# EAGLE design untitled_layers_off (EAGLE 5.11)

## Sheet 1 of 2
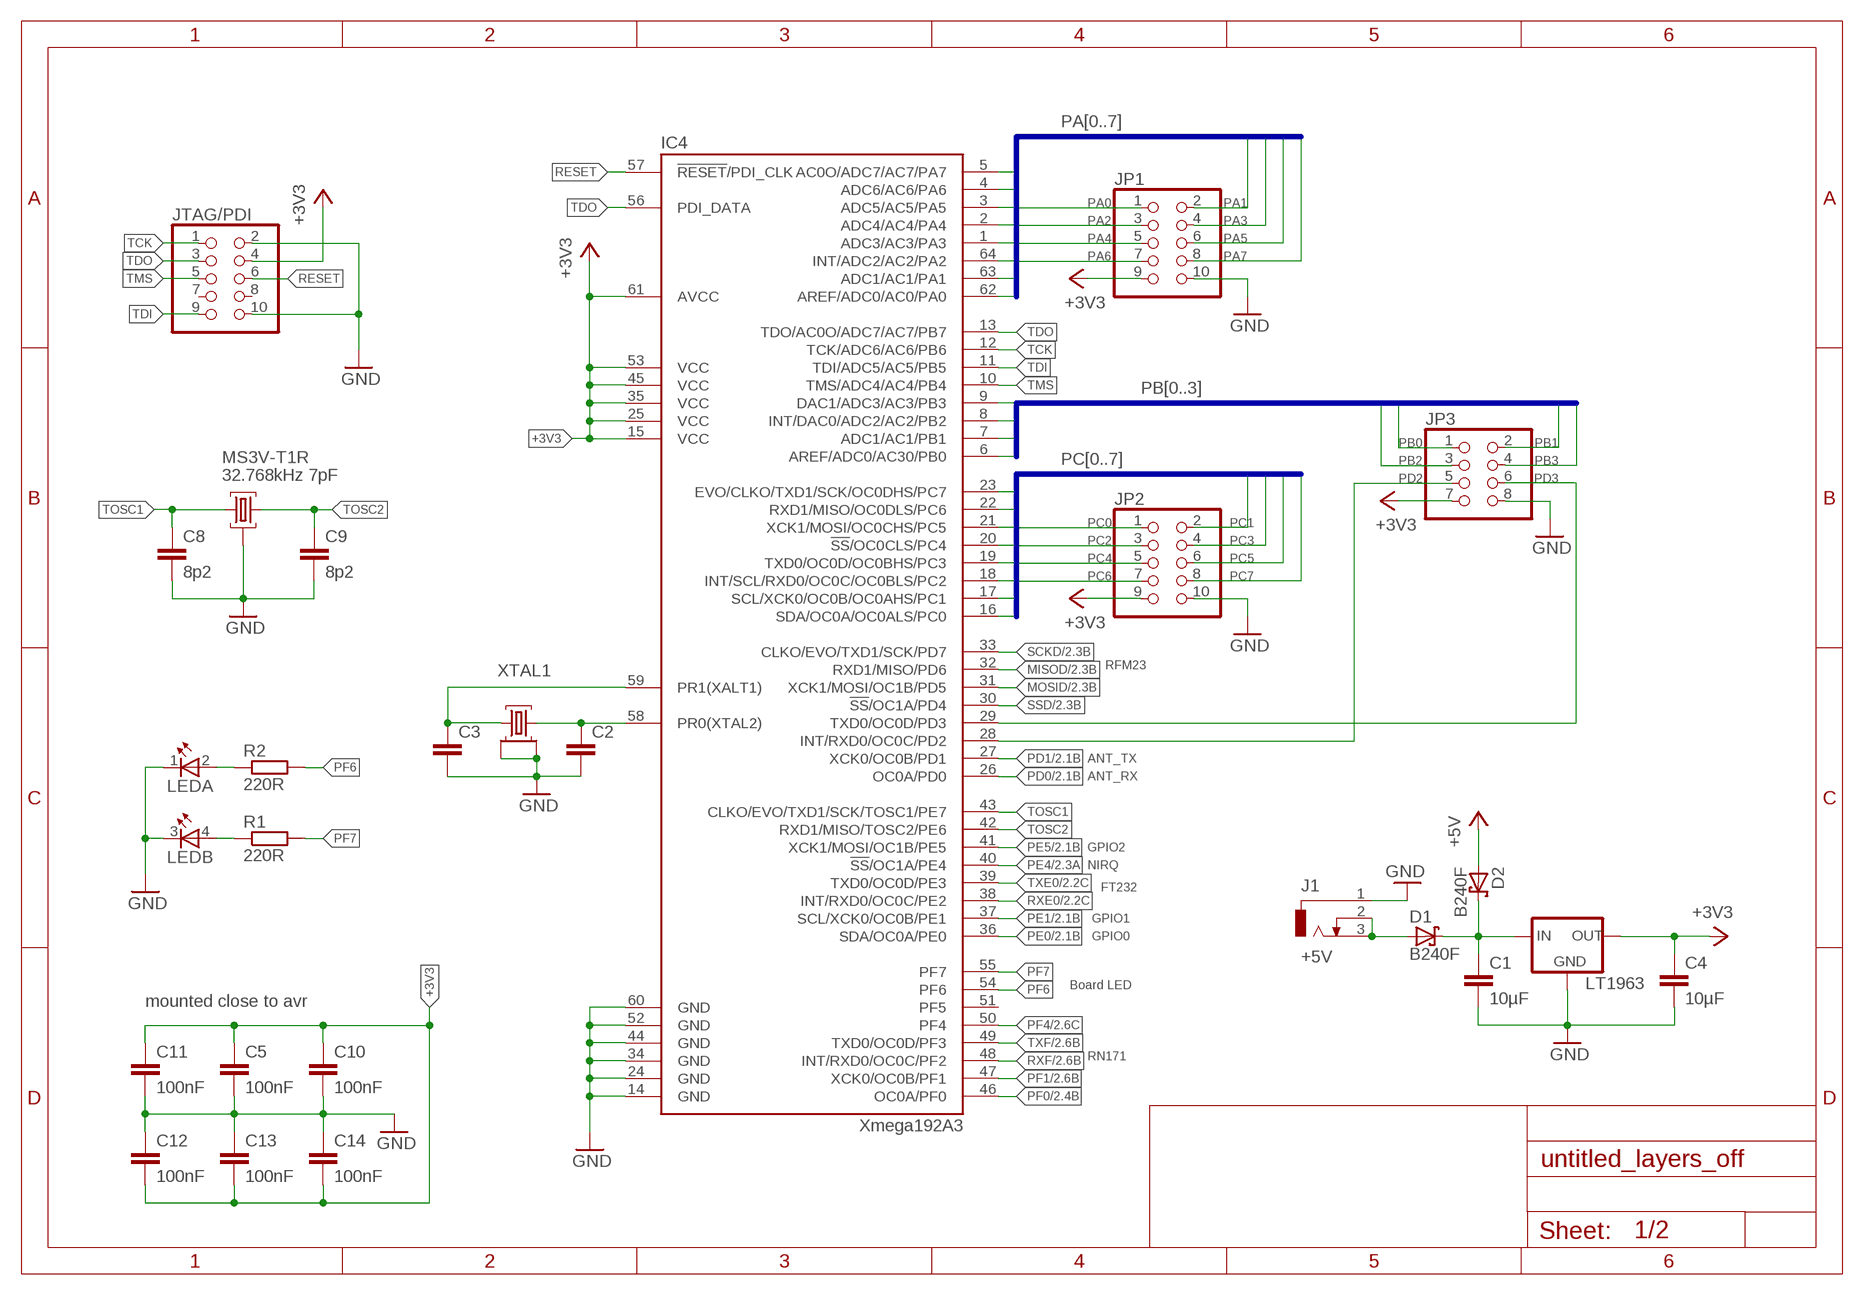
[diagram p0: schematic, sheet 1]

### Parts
C1  10µF  C-EUC1206  [C1206]
C2  C-EUC0805  [C0805]
C3  C-EUC0805  [C0805]
C4  10µF  C-EUC1206  [C1206]
C5  100nF  C-EUC0805  [C0805]
C8  8p2  C-EUC0805  [C0805]
C9  8p2  C-EUC0805  [C0805]
C10  100nF  C-EUC0805  [C0805]
C11  100nF  C-EUC0805  [C0805]
C12  100nF  C-EUC0805  [C0805]
C13  100nF  C-EUC0805  [C0805]
C14  100nF  C-EUC0805  [C0805]
D1  B240F  SCHOTTKY-DIODESMD  [SMB]
D2  B240F  SCHOTTKY-DIODESMD  [SMB]
IC4  Xmega192A3  ATXMEGA##A3-64A  [TQFP-64]
J1  +5V  DCJ0202  [DCJ0202]
JP1  PINHD-2X5  [2X05]
JP2  PINHD-2X5  [2X05]
JP3  PINHD-2X4  [2X04]
JTAG/PDI  PINHD-2X5/90  [2X05/90]
LED  TOPLED-2-/  [P-LCC-4/2]
LT1963  V_REG_MIC2920  [SOT223]
MS3V-T1R  32.768kHz 7pF  MS3V-T1R  [MS3V-T1R]
R1  220R  R-EU_R0805  [R0805]
R2  220R  R-EU_R0805  [R0805]
XTAL1  EUROQUARTZ-MT  [EUROQUARTZ-MT]

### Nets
+3V3: C4.1 C5.1 C10.1 C11.1 C12.2 C13.2 C14.2 IC4.15(VCC) IC4.25(VCC) IC4.35(VCC) IC4.45(VCC) IC4.53(VCC) IC4.61(AVCC) JP1.9 JP2.9 JP3.7 JTAG/PDI.4 LT1963.3(OUT) ; also sheet 2
+5V: D2.A ; also sheet 2
GND: C1.2 C2.2 C3.2 C4.2 C5.2 C8.2 C9.2 C10.2 C11.2 C12.1 C13.1 C14.1 IC4.14(GND) IC4.24(GND) IC4.34(GND) IC4.44(GND) IC4.52(GND) IC4.60(GND) J1.1 JP1.10 JP2.10 JP3.8 JTAG/PDI.2 JTAG/PDI.10 LED.1(A:C) LED.3(B:C) LT1963.2(GND) MS3V-T1R.TOP XTAL1.GND1 XTAL1.GND2 ; also sheet 2
MISOD: IC4.32(RXD1/MISO/PD6) ; also sheet 2
MOSID: IC4.31(XCK1/MOSI/OC1B/PD5) ; also sheet 2
N$1: LED.2(A:A) R2.1
N$2: D1.A J1.2 J1.3
N$3: C3.1 IC4.59(PR1(XALT1)) XTAL1.1
N$4: C2.1 IC4.58(PR0(XTAL2)) XTAL1.4
N$7: C1.1 D1.C D2.C LT1963.1(IN)
N$8: LED.4(B:A) R1.1
PA0: IC4.62(AREF/ADC0/AC0/PA0) JP1.1
PA1: IC4.63(ADC1/AC1/PA1) JP1.2
PA2: IC4.64(INT/ADC2/AC2/PA2) JP1.3
PA3: IC4.1(ADC3/AC3/PA3) JP1.4
PA4: IC4.2(ADC4/AC4/PA4) JP1.5
PA5: IC4.3(ADC5/AC5/PA5) JP1.6
PA6: IC4.4(ADC6/AC6/PA6) JP1.7
PA7: IC4.5(AC0O/ADC7/AC7/PA7) JP1.8
PB0: IC4.6(AREF/ADC0/AC30/PB0) JP3.1
PB1: IC4.7(ADC1/AC1/PB1) JP3.2
PB2: IC4.8(INT/DAC0/ADC2/AC2/PB2) JP3.3
PB3: IC4.9(DAC1/ADC3/AC3/PB3) JP3.4
PC0: IC4.16(SDA/OC0A/OC0ALS/PC0) JP2.1
PC1: IC4.17(SCL/XCK0/OC0B/OC0AHS/PC1) JP2.2
PC2: IC4.18(INT/SCL/RXD0/OC0C/OC0BLS/PC2) JP2.3
PC3: IC4.19(TXD0/OC0D/OC0BHS/PC3) JP2.4
PC4: IC4.20(!SS!/OC0CLS/PC4) JP2.5
PC5: IC4.21(XCK1/MOSI/OC0CHS/PC5) JP2.6
PC6: IC4.22(RXD1/MISO/OC0DLS/PC6) JP2.7
PC7: IC4.23(EVO/CLKO/TXD1/SCK/OC0DHS/PC7) JP2.8
PD0: IC4.26(OC0A/PD0) ; also sheet 2
PD1: IC4.27(XCK0/OC0B/PD1) ; also sheet 2
PD2: IC4.28(INT/RXD0/OC0C/PD2) JP3.5
PD3: IC4.29(TXD0/OC0D/PD3) JP3.6
PE0: IC4.36(SDA/OC0A/PE0) ; also sheet 2
PE1: IC4.37(SCL/XCK0/OC0B/PE1) ; also sheet 2
PE4: IC4.40(!SS!/OC1A/PE4) ; also sheet 2
PE5: IC4.41(XCK1/MOSI/OC1B/PE5) ; also sheet 2
PF0: IC4.46(OC0A/PF0) ; also sheet 2
PF1: IC4.47(XCK0/OC0B/PF1) ; also sheet 2
PF4: IC4.50(PF4) ; also sheet 2
PF6: IC4.54(PF6) R2.2
PF7: IC4.55(PF7) R1.2
RESET: IC4.57(!RESET!/PDI_CLK) JTAG/PDI.6
RXE0: IC4.38(INT/RXD0/OC0C/PE2) ; also sheet 2
RXF: IC4.48(INT/RXD0/OC0C/PF2) ; also sheet 2
SCKD: IC4.33(CLKO/EVO/TXD1/SCK/PD7) ; also sheet 2
SSD: IC4.30(!SS!/OC1A/PD4) ; also sheet 2
TCK: IC4.12(TCK/ADC6/AC6/PB6) JTAG/PDI.1
TDI: IC4.11(TDI/ADC5/AC5/PB5) JTAG/PDI.9
TDO: IC4.13(TDO/AC0O/ADC7/AC7/PB7) IC4.56(PDI_DATA) JTAG/PDI.3
TMS: IC4.10(TMS/ADC4/AC4/PB4) JTAG/PDI.5
TOSC1: C8.1 IC4.43(CLKO/EVO/TXD1/SCK/TOSC1/PE7) MS3V-T1R.P$2
TOSC2: C9.1 IC4.42(RXD1/MISO/TOSC2/PE6) MS3V-T1R.P$3
TXE0: IC4.39(TXD0/OC0D/PE3) ; also sheet 2
TXF: IC4.49(TXD0/OC0D/PF3) ; also sheet 2
Unconnected: IC4.51(PF5) JTAG/PDI.7 JTAG/PDI.8

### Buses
PA[0..7]
PC[0..7]
PB[0..3]

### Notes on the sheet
- RFM23
- ANT_TX
- ANT_RX
- GPIO2
- NIRQ
- FT232
- GPIO1
- GPIO0
- Board LED
- mounted close to avr
- RN171

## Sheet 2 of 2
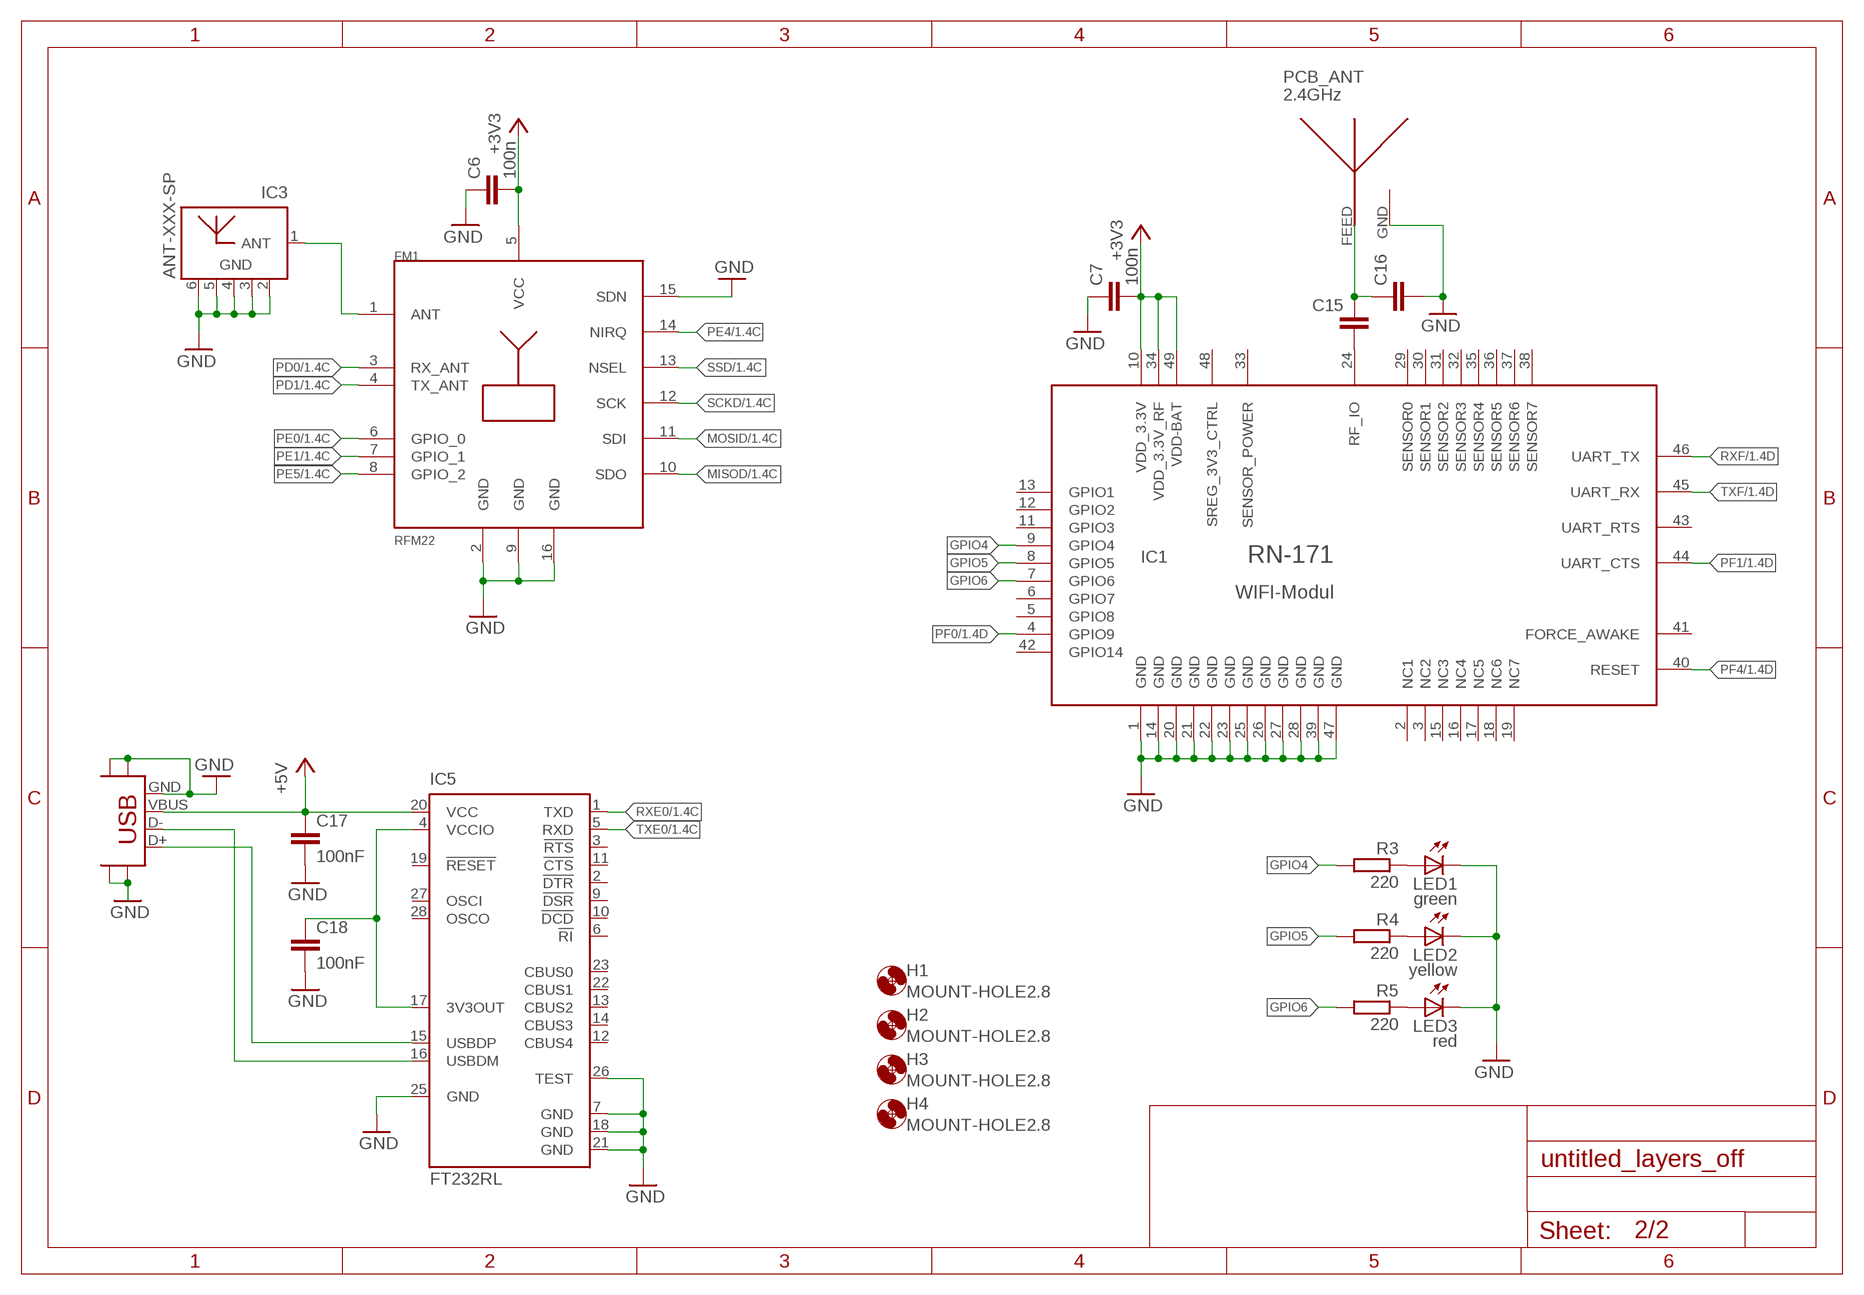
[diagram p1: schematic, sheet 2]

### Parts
C6  100n  C-EUC0805  [C0805]
C7  100n  C-EUC0805  [C0805]
C15  C-EUC0805  [C0805]
C16  C-EUC0805  [C0805]
C17  100nF  C-EUC0805  [C0805]
C18  100nF  C-EUC0805  [C0805]
FM1  RFM22  [RFM22]
H1  MOUNT-HOLE2.8  [2,8]
H2  MOUNT-HOLE2.8  [2,8]
H3  MOUNT-HOLE2.8  [2,8]
H4  MOUNT-HOLE2.8  [2,8]
IC1  RN-171  [RN-171]
IC3  ANT-XXX-SP  [ANT-XXX-SP]
IC5  FT232RL  [SSOP28]
LED1  green  LEDCHIPLED_0805  [CHIPLED_0805]
LED2  yellow  LEDCHIPLED_0805  [CHIPLED_0805]
LED3  red  LEDCHIPLED_0805  [CHIPLED_0805]
PCB_ANT  2.4GHz  ANT_2G4  [ANT_2G4]
R3  220  R-EU_R0805  [R0805]
R4  220  R-EU_R0805  [R0805]
R5  220  R-EU_R0805  [R0805]
X2  USBSMD  [USB-MINIB]

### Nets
+3V3: C6.2 C7.2 FM1.5(VCC) IC1.10(VDD_3.3V) IC1.34(VDD_3.3V_RF) IC1.49(VDD-BAT) ; also sheet 1
+5V: C17.1 IC5.20(VCC) X2.VBUS ; also sheet 1
GND: C6.1 C7.1 C16.2 C17.2 C18.2 FM1.2(GND) FM1.9(GND) FM1.15(SDN) FM1.16(GND) IC1.1(GND) IC1.14(GND) IC1.20(GND) IC1.21(GND) IC1.22(GND) IC1.23(GND) IC1.25(GND) IC1.26(GND) IC1.27(GND) IC1.28(GND) IC1.39(GND) IC1.47(GND) IC3.2(GND) IC3.3(GND) IC3.4(GND) IC3.5(GND) IC3.6(GND) IC5.7(GND) IC5.18(GND) IC5.21(GND) IC5.25(GND) IC5.26(TEST) LED1.C LED2.C LED3.C PCB_ANT.GND X2.GND X2.S1 X2.S2 X2.S3 X2.S4 ; also sheet 1
GPIO4: IC1.9(GPIO4) R3.2
GPIO5: IC1.8(GPIO5) R4.2
GPIO6: IC1.7(GPIO6) R5.2
MISOD: FM1.10(SDO) ; also sheet 1
MOSID: FM1.11(SDI) ; also sheet 1
N$9: C15.2 IC1.24(RF_IO)
N$13: FM1.1(ANT) IC3.1(ANT)
N$16: LED1.A R3.1
N$17: LED2.A R4.1
N$18: LED3.A R5.1
N$31: C15.1 C16.1 PCB_ANT.FEED
N$39: IC5.16(USBDM) X2.D-
N$40: IC5.15(USBDP) X2.D+
N$47: C18.1 IC5.4(VCCIO) IC5.17(3V3OUT)
PD0: FM1.3(RX_ANT) ; also sheet 1
PD1: FM1.4(TX_ANT) ; also sheet 1
PE0: FM1.6(GPIO_0) ; also sheet 1
PE1: FM1.7(GPIO_1) ; also sheet 1
PE4: FM1.14(NIRQ) ; also sheet 1
PE5: FM1.8(GPIO_2) ; also sheet 1
PF0: IC1.4(GPIO9) ; also sheet 1
PF1: IC1.44(UART_CTS) ; also sheet 1
PF4: IC1.40(RESET) ; also sheet 1
RXE0: IC5.1(TXD) ; also sheet 1
RXF: IC1.46(UART_TX) ; also sheet 1
SCKD: FM1.12(SCK) ; also sheet 1
SSD: FM1.13(NSEL) ; also sheet 1
TXE0: IC5.5(RXD) ; also sheet 1
TXF: IC1.45(UART_RX) ; also sheet 1
Unconnected: IC1.2(NC1) IC1.3(NC2) IC1.5(GPIO8) IC1.6(GPIO7) IC1.11(GPIO3) IC1.12(GPIO2) IC1.13(GPIO1) IC1.15(NC3) IC1.16(NC4) IC1.17(NC5) IC1.18(NC6) IC1.19(NC7) IC1.29(SENSOR0) IC1.30(SENSOR1) IC1.31(SENSOR2) IC1.32(SENSOR3) IC1.35(SENSOR4) IC1.36(SENSOR5) IC1.37(SENSOR6) IC1.38(SENSOR7) IC1.41(FORCE_AWAKE) IC1.42(GPIO14) IC1.43(UART_RTS) IC5.2(!DTR) IC5.3(!RTS) IC5.6(!RI) IC5.9(!DSR) IC5.10(!DCD) IC5.11(!CTS) IC5.12(CBUS4) IC5.13(CBUS2) IC5.14(CBUS3) IC5.19(!RESET) IC5.22(CBUS1) IC5.23(CBUS0) IC5.27(OSCI) IC5.28(OSCO)

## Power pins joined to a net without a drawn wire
SENSOR_POWER: IC1.33(SENSOR_POWER)
SREG_3V3_CTRL: IC1.48(SREG_3V3_CTRL)

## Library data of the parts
C1-C18 = rcl:C-EU: CAPACITOR, European symbol
D1 D2 = diode:SCHOTTKY-DIODE: Schottky Diode
FM1 = RFMxx:RFM22
H1-H4 = holes:MOUNT-HOLE: MOUNTING HOLE with drill center marker
IC1 = RN-171:RN-171
IC3 = linx:ANT-XXX-SP: ANT-315-SP Source: http://www.antennafactor.com/documents/ANT-315-SP_Data_Sheet.pdf; OC_FARNELL: unknown; OC_NEWARK: unknown
IC4 = ATxmega__A3:ATXMEGA##A3
IC5 = ftdichip:FT232R: Source: http://www.ftdichip.com/Documents/DataSheets/DS_FT232R_v104.pdf; MPN: FT232RL; OC_FARNELL: 1146032; OC_NEWARK: 91K9918
J1 = con-jack:DCJ0202: DC POWER JACK Source: DCJ0202.pdf; OC_FARNELL: unknown; OC_NEWARK: unknown
JP1 JP2 JTAG/PDI = pinhead:PINHD-2X5: PIN HEADER
JP3 = pinhead:PINHD-2X4: PIN HEADER
LED = led:TOPLED-2-: Multi TOPLED® (two color) LG T672, LP T672 LSY T67B LSW T67C LSY T675 LSY T676 LSG T677 LSG T770 Source: http://www.osram.convergy.de/
LED1-LED3 = led:LED: LED
LT1963 = SparkFun:V_REG_MIC2920: MIC2920A (http://www.micrel.com/_PDF/mic2920.pdf) - 400mA output LDO Regulator
MS3V-T1R = studienarbeit:MS3V-T1R: MICRO CRYSTAL MS3V-T1R
PCB_ANT = studienarbeit:ANT_2G4
R1-R5 = rcl:R-EU_: RESISTOR, European symbol
X2 = SparkFun:USB: USB Connectors USB-B-PTH is fully proven SKU : PRT-00139 USB-miniB is fully proven SKU : PRT-00587 USB-A-PCB is untested. USB-A-H is throughly reviewed, but untested. Spark Fun Electronics SKU : PRT-00437 USB-B-SMT is throughly reviewed, but untested. Needs silkscreen touching up. USB-A-S has not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
XTAL1 = studienarbeit:EUROQUARTZ-MT

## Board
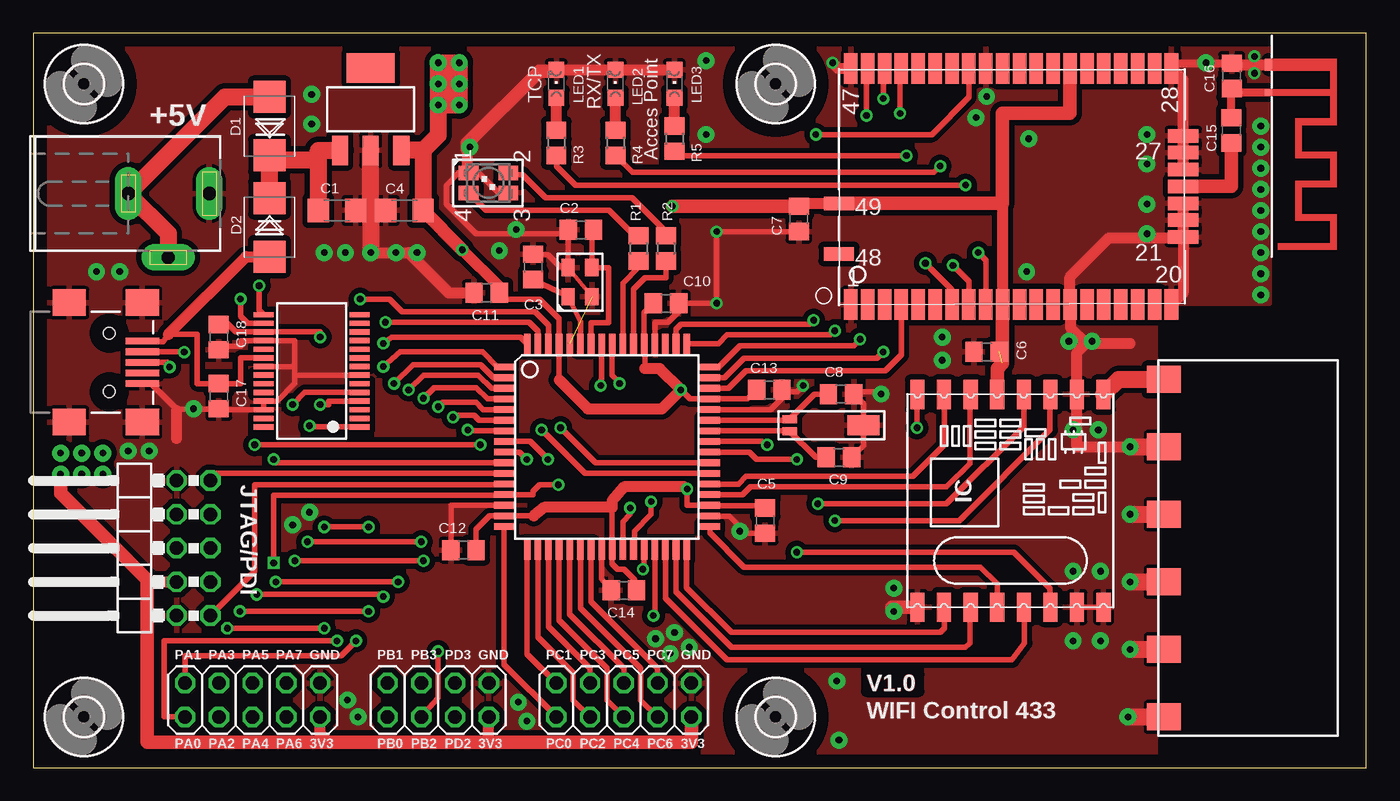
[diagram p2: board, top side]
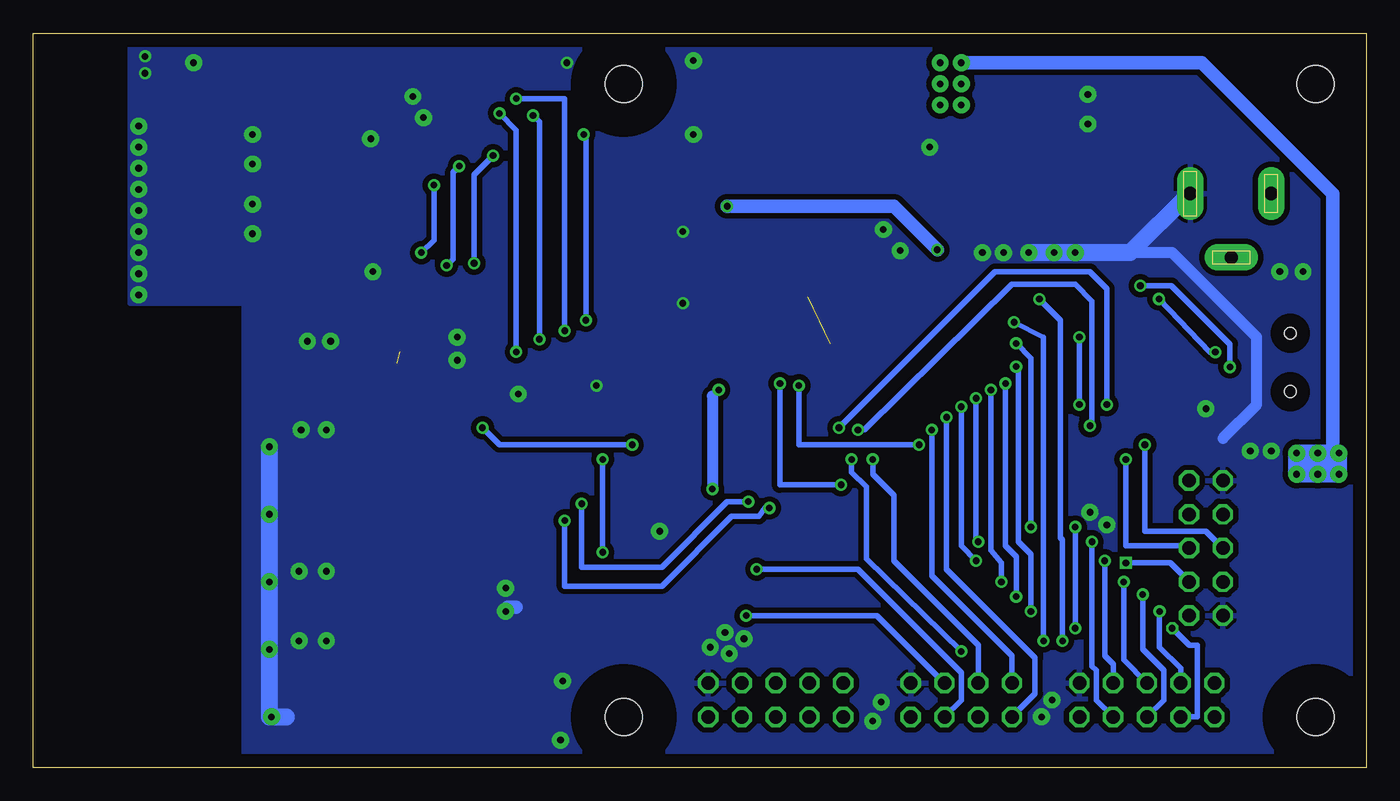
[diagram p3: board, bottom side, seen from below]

Size 100.33 x 55.24 mm. Coordinates in mm from the lower left corner, seen from the top.
Outline: 0,0 100.31,0 100.33,55.24 0,55.24 0,0
Copper layers (1*16): Top 0.035mm / dielectric 1.5mm / Bottom 0.035mm
Design rules "default *": minimum track width 0.15mm, minimum drill 0.3mm, track to track 8mil, track to pad 8mil, pad to pad 8mil, via to via 8mil, smd to smd 8mil, copper to edge 40mil, drill to drill 8mil, minimum pad ring 10mil, minimum via ring 8mil, stop-mask expansion 4mil, vias tented up to drill 0mil, thermal gap 10mil

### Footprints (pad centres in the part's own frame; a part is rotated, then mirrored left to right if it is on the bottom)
C1206 = smd 1.6 x 1.8: 1 -1.4,0; 2 1.4,0
C0805 = smd 1.3 x 1.5: 1 -0.95,0; 2 0.95,0
SMB = smd 2.4 x 2.4: A 2.2,0; C -2.2,0
RFM22 = smd 2.184 x 1.067: 1 -8.38,5.62; 2 -8.38,3.62; 3 -8.38,1.62; 4 -8.38,-0.38; 5 -8.38,-2.38; 6 -8.38,-4.38; 7 -8.38,-6.38; 8 -8.38,-8.38; 9 7.62,-8.38; 10 7.62,-6.38; 11 7.62,-4.38; 12 7.62,-2.38; 13 7.62,-0.38; 14 7.62,1.62; 15 7.625,3.625; 16 7.625,5.625
2,8 = hole 2.8: 0,0
RN-171 = smd 1.016 x 2.286: 1 -11.43,-7.62; 2 -10.16,-7.62; 3 -8.89,-7.62; 4 -7.62,-7.62; 5 -6.35,-7.62; 6 -5.08,-7.62; 7 -3.81,-7.62; 8 -2.54,-7.62; 9 -1.27,-7.62; 10 0,-7.62; 11 1.27,-7.62; 12 2.54,-7.62; 13 3.81,-7.62; 14 5.08,-7.62; 15 6.35,-7.62; 16 7.62,-7.62; 17 8.89,-7.62; 18 10.16,-7.62; 19 11.43,-7.62; 20 12.7,-7.62; 28 12.7,10.16; 29 11.43,10.16; 30 10.16,10.16; 31 8.89,10.16; 32 7.62,10.16; 33 6.35,10.16; 34 5.08,10.16; 35 3.81,10.16; 36 2.54,10.16; 37 1.27,10.16; 38 0,10.16; 39 -1.27,10.16; 40 -2.54,10.16; 41 -3.81,10.16; 42 -5.08,10.16; 43 -6.35,10.16; 44 -7.62,10.16; 45 -8.89,10.16; 46 -10.16,10.16; 47 -11.43,10.16 | smd 2.286 x 1.016: 21 13.589,-2.54; 22 13.589,-1.27; 23 13.589,0; 24 13.589,1.27; 25 13.589,2.54; 26 13.589,3.81; 27 13.589,5.08; 48 -12.319,-3.81; 49 -12.319,0
ANT-XXX-SP = smd 2.032 x 2.54: 1 -12.7,0; 2 -7.62,0; 3 -2.54,0; 4 2.54,0; 5 7.62,0; 6 12.7,0
TQFP-64 = smd 1.5 x 0.5: 1 -7.75,6; 2 -7.75,5.2; 3 -7.75,4.4; 4 -7.75,3.6; 5 -7.75,2.8; 6 -7.75,2; 7 -7.75,1.2; 8 -7.75,0.4; 9 -7.75,-0.4; 10 -7.75,-1.2; 11 -7.75,-2; 12 -7.75,-2.8; 13 -7.75,-3.6; 14 -7.75,-4.4; 15 -7.75,-5.2; 16 -7.75,-6; 33 7.75,-6; 34 7.75,-5.2; 35 7.75,-4.4; 36 7.75,-3.6; 37 7.75,-2.8; 38 7.75,-2; 39 7.75,-1.2; 40 7.75,-0.4; 41 7.75,0.4; 42 7.75,1.2; 43 7.75,2; 44 7.75,2.8; 45 7.75,3.6; 46 7.75,4.4; 47 7.75,5.2; 48 7.75,6 | smd 0.5 x 1.5: 17 -6,-7.75; 18 -5.2,-7.75; 19 -4.4,-7.75; 20 -3.6,-7.75; 21 -2.8,-7.75; 22 -2,-7.75; 23 -1.2,-7.75; 24 -0.4,-7.75; 25 0.4,-7.75; 26 1.2,-7.75; 27 2,-7.75; 28 2.8,-7.75; 29 3.6,-7.75; 30 4.4,-7.75; 31 5.2,-7.75; 32 6,-7.75; 49 6,7.75; 50 5.2,7.75; 51 4.4,7.75; 52 3.6,7.75; 53 2.8,7.75; 54 2,7.75; 55 1.2,7.75; 56 0.4,7.75; 57 -0.4,7.75; 58 -1.2,7.75; 59 -2,7.75; 60 -2.8,7.75; 61 -3.6,7.75; 62 -4.4,7.75; 63 -5.2,7.75; 64 -6,7.75
SSOP28 = smd 0.4 x 1.5: 1 -4.225,-3.625; 2 -3.575,-3.625; 3 -2.925,-3.625; 4 -2.275,-3.625; 5 -1.625,-3.625; 6 -0.975,-3.625; 7 -0.325,-3.625; 8 0.325,-3.625; 9 0.975,-3.625; 10 1.625,-3.625; 11 2.275,-3.625; 12 2.925,-3.625; 13 3.575,-3.625; 14 4.225,-3.625; 15 4.225,3.625; 16 3.575,3.625; 17 2.925,3.625; 18 2.275,3.625; 19 1.625,3.625; 20 0.975,3.625; 21 0.325,3.625; 22 -0.325,3.625; 23 -0.975,3.625; 24 -1.625,3.625; 25 -2.275,3.625; 26 -2.925,3.625; 27 -3.575,3.625; 28 -4.225,3.625
DCJ0202 = drill 1 pad 2 long: 1 0,3.1; 2 4.8,0; 3 0,-3
2X05 = drill 1.016 octagon: 1 -5.08,-1.27; 2 -5.08,1.27; 3 -2.54,-1.27; 4 -2.54,1.27; 5 0,-1.27; 6 0,1.27; 7 2.54,-1.27; 8 2.54,1.27; 9 5.08,-1.27; 10 5.08,1.27
2X04 = drill 1.016 octagon: 1 -3.81,-1.27; 2 -3.81,1.27; 3 -1.27,-1.27; 4 -1.27,1.27; 5 1.27,-1.27; 6 1.27,1.27; 7 3.81,-1.27; 8 3.81,1.27
2X05/90 = drill 1.016 octagon: 1 -5.08,-6.35; 2 -5.08,-3.81; 3 -2.54,-6.35; 4 -2.54,-3.81; 5 0,-6.35; 6 0,-3.81; 7 2.54,-6.35; 8 2.54,-3.81; 9 5.08,-6.35; 10 5.08,-3.81
P-LCC-4/2 = smd 1.1 x 1.5: 1 -0.75,-1.5; 2 -0.75,1.5; 3 0.75,1.5; 4 0.75,-1.5
CHIPLED_0805 = smd 1.2 x 1.2: A 0,-1.05; C 0,1.05
SOT223 = smd 1.219 x 2.235: 1 -2.311,-3.099; 2 0,-3.099; 3 2.311,-3.099 | smd 3.6 x 2.2: 4 0,3.099
MS3V-T1R = smd 1.1 x 0.6: P$2 4.35,0.3; P$3 4.35,1.2 | smd 2.4 x 1.5: TOP -1.2,0.75
ANT_2G4 = smd 0.5 x 0.5: FEED 2.55,0.25 | smd 0.9 x 0.5: GND 0.45,0.25
R0805 = smd 1.3 x 1.5: 1 -0.95,0; 2 0.95,0
USB-MINIB = smd 2.5 x 0.5: D+ 2.5,0; D- 2.5,0.8; GND 2.5,-1.6; ID 2.5,-0.8; VBUS 2.5,1.6 | smd 2.5 x 2: S1 -3,4.5; S2 2.5,4.5; S3 -3,-4.5; S4 2.5,-4.5 | hole 0.9: 0,2.2; 0,-2.2
EUROQUARTZ-MT = smd 1.3 x 1: 1 0.65,2.3; 4 2.85,0.5; GND1 2.85,2.3; GND2 0.65,0.5

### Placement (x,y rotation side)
C1  22.86,41.91 0 top
C2  41.22,40.45 180 top
C3  37.63,37.66 90 top
C4  27.94,41.91 180 top
C5  55.09,18.57 270 top
C6  71.76,31.27 0 top
C7  57.63,41.28 90 top
C8  60.8,28.1 0 top
C9  60.64,23.34 0 top
C10  47.62,34.92 0 top
C11  34.13,35.72 180 top
C12  32.38,16.35 0 top
C13  55.4,28.42 180 top
C14  44.45,13.34 0 top
C15  90.17,47.94 270 top
C16  90.2,52.04 90 top
C17  13.97,27.94 270 top
C18  13.97,32.38 270 top
D1  17.78,48.26 90 top
D2  17.78,40.64 270 top
FM1  74.93,19.68 270 top
H1  3.81,51.44 0 top
H2  55.88,51.44 0 top
H3  3.81,3.81 0 top
H4  55.88,3.81 0 top
IC1  72.96,42.45 0 top
IC3  85.09,16.51 270 top
IC4  43.18,24.13 0 top
IC5  20.95,29.84 90 top
J1  10.16,43.18 270 top
JP1  16.51,5.08 0 top
JP2  44.45,5.08 0 top
JP3  30.48,5.08 0 top
JTAG/PDI  6.99,16.51 90 top
LED  34.26,43.98 270 top
LED1  39.37,51.44 0 top
LED2  43.81,51.44 0 top
LED3  48.26,51.44 0 top
LT1963  25.4,49.53 0 top
MS3V-T1R  61.28,26.51 180 top
PCB_ANT  92.71,53.34 270 top
R1  45.56,39.05 270 top
R2  47.63,39.06 270 top
R3  39.37,46.99 270 top
R4  43.81,46.99 270 top
R5  48.26,47.31 270 top
X2  5.71,30.48 0 top
XTAL1  42.55,34.77 90 top

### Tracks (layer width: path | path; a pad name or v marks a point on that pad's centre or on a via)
+3V3  (via drill 0.5, 0.5 pad 1.27)  (1 unrouted)
  Top 0.406: C10.1 45.98,34.23 IC4.53 46.04,31.82 46.04,30 | C12.2 33.34,17.94 34.33,18.93 IC4.15 37.66,18.93 | 43.58,19.57 IC4.25 43.58,15.32 43.97,14.92 44.45,14.92 45.24,14.13 45.24,13.65 C14.2 | v48.74,28.42 49.42,27.73 IC4.45 53.77,27.73 C13.2 | C11.1 35.56,35.24 38.1,35.24 39.58,33.76 IC4.61 39.58,29.16 | 49.05,21.11 v49.21,20.95 49.21,19.73 IC4.35 50.98,19.68 51.91,19.68 52.07,19.68 54.93,19.68 C5.1
  Top 0.61: IC1.34 78.26,52.6
  Top 0.813: 72.96,42.45 IC1.10 | C7.2 57.63,42.45 IC1.49 | C11.1 35.08,36.17 v32.29,38.96 | 37.66,18.93 38.46,19.57 43.58,19.57 43.58,20.09 44.45,21.11 49.05,21.11 | 39.58,29.16 41.75,26.99 47.31,26.99 v48.74,28.42 47.15,30 46.04,30 | JP1.9 21.59,2.54 22.23,1.91 | 34.29,1.91 33.97,1.91 34.29,2.22 JP3.7 | 8.57,13.97 JTAG/PDI.4 | 22.23,1.91
  Top 1.016: IC1.34 78.04,49.21 72.96,49.21 72.96,42.45 IC1.49 | C7.2 50.64,42.23 v48.1,42.23 | C4.1 v32.29,38.96 | IC1.10 72.96,30.41 72.55,30 FM1.5 | 34.29,1.91 22.23,1.91 8.57,1.91 8.57,13.97 8.57,14.13 2.06,20.64 v2.06,22.07 | JP2.9 49.53,1.91 33.97,1.91
  Top 1.27: 29.34,46.43 LT1963.3 | 29.34,46.43 C4.1 | 29.34,46.43 30.48,47.57 v30.48,49.85 | v30.48,49.85 30.48,51.28 v30.48,51.44 v30.48,53.02 v32.07,53.02 v32.07,51.44 | v32.07,51.44 v32.07,49.85 v30.48,49.85 | v30.48,49.85 31.27,50.64 31.27,52.86 32.07,52.07 v32.07,51.44
  Bottom 0.406: v48.74,28.42 49.21,27.94
  Bottom 0.813: 49.21,27.94 v49.21,20.95
  Bottom 1.016: v48.1,42.23 35.56,42.23 v32.29,38.96 | v30.48,53.02 12.38,53.02 2.54,43.18 2.54,23.5
  Bottom 1.27: v2.06,23.65 2.38,23.65 2.54,23.5 2.7,23.65 | 2.7,23.65 v3.65,23.65 | v3.65,23.65 v5.24,23.65 v5.24,22.07 v3.65,22.07 | v2.06,22.07 v3.65,22.07 | v2.06,23.65 2.7,23.65 | v2.06,22.07 v2.06,23.65 | v2.06,22.07 2.86,22.86 4.45,22.86 v3.65,22.07 | v2.06,23.65 v3.65,23.65
+5V
  Top 0.406: IC5.20 15.63,30.82 15.63,28.89 C17.1 | C17.1 | C17.1 12.36,28.89 12.36,32.58 10.16,32.58 9.77,32.02 9.1,32.03 9.03,32.08 X2.VBUS
  Top 0.813: D2.A 16.02,38.44 10.16,32.58
GND  (via drill 0.5, 0.5 pad 0.3, 0.5 pad 1.27)  (1 unrouted)
  Top 0.305: XTAL1.GND1 XTAL1.GND2
  Top 0.406: 10.79,26.97 10.69,26.97 10.79,26.86 | 10.79,26.97 13.97,26.97 | 13.97,26.97 C17.2 | 13.97,26.97 13.97,26.92 IC5.26 IC5.25 18.36,27.57 19.68,28.89 19.68,29.52 | C18.2 13.97,31.7 15.64,31.7 15.64,32.12 IC5.18 19.68,32.12 19.68,30.17 | 19.68,30.17 IC5.21 | 19.68,29.52 IC5.7 | 19.68,29.52 19.68,30.17 | X2.GND 8.88,28.88 10.79,26.97 | 40.24,37.66 40.24,39.97 C2.2 39.99,40.16 33.34,40.16 31.11,42.39 31.11,43.81 32.03,44.73 LED.1 32.79,44.77 33.5,44.77 35.03,43.23 LED.3 | 40.24,37.66 XTAL1.GND1 | FM1.15 FM1.16 | C5.2 53.66,17.62 52.39,18.89 50.97,18.89 IC4.34 | C12.1 31.43,19.73 IC4.14 | C9.2 62.48,24.22 MS3V-T1R.TOP 62.48,27.37 C8.2 61.91,28.26 63.5,28.26 | IC4.44 55.51,26.93 56.52,27.94 56.52,28.25 | 56.52,28.25 C13.1 | IC4.24 42.78,14.21 C14.1 | 40.24,37.66 39.65,37.66 38.73,38.58 37.67,38.58 C3.2 | C7.1 v51.44,40.32 v51.44,34.92 C10.2 48.58,34.29 47.78,33.5 46.83,33.5 46.78,33.45 IC4.52 | 56.52,28.25 57.47,28.25 v57.94,28.73
  Top 0.61: C16.2 85.66,52.99 IC1.28
  Top 0.813: 10.79,24.77 10.79,26.86 | PCB_ANT.GND 90.36,52.89 C16.2 | LED1.C LED2.C LED3.C | C11.2 31.27,35.72 28.26,38.73 v27.3,38.73 v25.4,38.73 | 32.7,46.51 32.7,44.79 LED.1 | IC1.23 IC1.22 IC1.21 | IC1.21 86.55,35.71 IC1.20 | 79.22,31.91 82.55,31.91 | 79.22,31.91 78.11,33.02 78.11,34.13 | IC1.14 78.04,36.92 80.96,39.85 86.49,39.85 IC1.21 | IC1.25 IC1.26 IC1.27 86.55,51.72 IC1.28 | IC1.47 60.58,52.6 v60.17,53.02 | 79.22,31.91 78.55,31.24 FM1.2 78.55,24.13 v82.55,24.13
  Top 1.016: 64.61,12.06 FM1.9 | 32.7,46.51 32.7,46.99 38.1,52.39 39.27,52.39 LED1.C
  Top 1.27: 25.4,41.91 v25.4,38.73 | 25.4,41.91 LT1963.2 | C1.2 25.4,41.91 | 25.4,41.91 C4.2 | 82.55,3.81 IC3.6 | v82.55,8.89 IC3.5 | v82.55,13.97 IC3.4 | v82.55,19.05 IC3.3 | v82.55,24.13 IC3.2
  Bottom 0.813: 17.78,38.73 14.61,38.73 8.26,32.38 8.26,27.3 10.79,24.77
  Bottom 1.016: 63.98,12.06 64.61,12.06
  Bottom 1.27: J1.1 13.34,43.18 17.78,38.73 v21.91,38.73 v23.5,38.73 v25.4,38.73 | 81.28,3.81 82.55,3.81 v82.55,24.13
  other vias: 91.92,53.5 91.92,52.23 46.83,9.68 48.26,10.16 47.94,8.57 49.37,9.05 23.65,5.08 24.45,3.81 36.51,4.92 37.15,3.49 60.48,6.51 60.64,2.06 28.89,38.73 35.08,38.89 36.35,40.48 92.39,35.56 92.39,43.5 92.39,41.91 92.39,40.32 92.39,38.73 92.39,37.15 92.39,45.09 92.39,46.67 92.39,48.26 88.27,53.02 83.82,47.62 83.82,45.4 83.82,42.39 83.82,40.16 77.95,32.07 7.14,23.81 8.73,23.81 4.76,37.31 6.51,37.31 20.8,19.21 19.53,18.26 64.77,13.49 64.77,11.75 80.33,14.76 78.26,14.76 78.26,9.53 80.33,9.53 82.39,3.81 79.69,32.07 78.26,25.4 80.17,25.4 53.18,17.78 68.42,32.38 68.42,30.64 71.75,50.48 70.96,48.9 74.93,47.31 74.77,37.31 20.95,48.42 20.95,50.64 12.06,26.99 50.64,47.62 50.64,53.18 32.86,46.67 63.82,28.1
  pour Bottom (isolate 0.406): 0,0 0,55.24 93.03,55.24 93.03,34.92 84.45,34.92 84.45,0
  pour Top (isolate 0.406): 0,55.24 93.03,55.24 93.03,34.92 84.45,34.92 84.45,0 0,0
GPIO4  (via drill 0.5)
  Top 0.406: R3.2 39.37,45.24 40.8,43.81 v70.17,43.81 | v71.12,38.73 71.69,38.17 IC1.9
  Bottom 0.406: v70.17,43.81 70.17,39.69 v71.12,38.73
GPIO5  (via drill 0.5)
  Top 0.406: R4.2 45.09,44.77 67.79,44.77 v68.26,45.24 | v68.26,45.24 | v69.22,37.78 70.42,36.58 IC1.8
  Bottom 0.406: v68.26,45.24 68.74,44.77 68.74,38.26 v69.22,37.78
GPIO6  (via drill 0.5)
  Top 0.406: R5.2 48.58,46.04 v65.72,46.04 | v67.15,37.94 69.15,35.95 IC1.7
  Bottom 0.406: v65.72,46.04 67.15,44.61 v67.15,37.94
MISOD
  Top 0.406: IC4.32 49.18,13.53 52.55,10.16 68.26,10.16 68.58,10.48 68.58,12.04 FM1.10
MOSID
  Top 0.406: IC4.31 48.38,13.21 52.55,9.05 70.17,9.05 70.48,9.37 70.48,12 FM1.11
N$1
  Top 0.406: R2.1 47.62,40.32 45.09,42.86 38.58,42.86 36.83,44.61 35.88,44.61 LED.2
N$2
  Top 1.27: J1.2 10.16,40.18 J1.3 14.44,50.46 D1.A
N$3
  Top 0.406: IC4.59 41.18,33.53 XTAL1.1 40.24,35.44 C3.1
N$4
  Top 0.406: IC4.58 41.98,33.46 43.31,33.46 43.31,37.62 XTAL1.4 42.05,39.97 C2.1
N$7
  Top 1.27: 17.78,45.72 D1.C | LT1963.1 21.46,46.43 21.46,45.72 | 21.46,45.72 C1.1 | D2.C 17.78,45.72 | 17.78,45.72 21.46,45.72
N$8
  Top 0.406: R1.1 45.25,40 43.34,41.91 34.08,41.91 LED.4
N$9
  Top 1.016: C15.2 90.17,43.72 IC1.24
N$13
  Top 1.27: FM1.1 81.69,29.21 IC3.1
N$16
  Top 0.813: R3.1 LED1.A
N$17
  Top 0.813: R4.1 LED2.A
N$18
  Top 0.813: R5.1 LED3.A
N$31
  Top 0.61: PCB_ANT.FEED 90.36,50.79 C16.1 90.17,51.09 C15.1
N$39  (via drill 0.5)
  Top 0.406: X2.D- 11.17,31.28 v11.36,31.25 | v15.6,35.25 15.6,33.95 16.13,33.42 IC5.16
  Bottom 0.406: v11.36,31.25 11.76,31.25 v15.6,35.25
N$40  (via drill 0.5)
  Top 0.406: X2.D+ 10.07,30.48 v10.26,30.13 | v17,36.25 17,34.4 IC5.15
  Bottom 0.406: v10.26,30.13 10.26,31.85 14.66,36.25 v17,36.25
N$47  (via drill 0.5)
  Top 0.406: C18.1 14.47,33.54 15.25,32.77 IC5.17 21.59,32.77 v21.59,32.38 | v21.59,27.3 22.23,27.3 22.23,27.57 IC5.4
  Bottom 0.406: v21.59,32.38 v21.59,27.3
PA0  (via drill 0.5)
  Top 0.406: IC4.62 38.78,33.29 37.78,34.29 27.78,34.29 26.83,35.24 v24.61,35.24 | v22.86,9.53 9.84,9.53 9.84,3.81 JP1.1
  Bottom 0.406: v24.61,35.24 23.02,33.66 23.02,17.3 22.86,17.14 v22.86,9.53
PA1  (via drill 0.5)
  Top 0.406: IC4.63 37.98,32.82 37.31,33.5 v26.51,33.5 | v24.29,9.53 23.18,8.41 11.43,8.41 JP1.2
  Bottom 0.406: v26.51,33.5 24.29,32.38 24.29,16.67 24.29,16.51 v24.29,9.53
PA2  (via drill 0.5)
  Top 0.406: IC4.64 36.67,32.38 26.99,32.38 v26.35,31.91 | v21.91,18.1 v25.24,18.1 | v14.61,10.48 v21.91,10.48
  Bottom 0.406: JP1.3 12.7,3.81 12.7,9.21 13.34,9.21 v14.61,10.48 | v21.91,10.48 v21.91,18.1 | v25.24,18.1 25.24,30.8 v26.35,31.91
PA3  (via drill 0.5)
  Top 0.406: IC4.1 34.96,30.13 33.81,31.27 27.62,31.27 v26.35,30.16 | v15.56,11.75 v25.24,11.75
  Bottom 0.406: v26.35,30.16 26.19,30 26.19,29.05 26.19,16.99 25.24,16.03 v25.24,11.75 | v15.56,11.75 15.56,9.05 13.97,7.46 JP1.4
PA4  (via drill 0.5)
  Top 0.406: IC4.2 34.65,29.33 33.66,30.32 28.57,30.32 v27.15,28.89 | v26.35,12.86 26.19,13.02 v16.83,13.02
  Bottom 0.406: v27.15,28.89 27.15,16.67 26.35,15.88 v26.35,12.86 | v16.83,13.02 16.83,8.89 15.24,7.3 15.24,5.08 JP1.5
PA5  (via drill 0.5)
  Top 0.406: IC4.3 34.49,28.53 33.5,29.53 29.37,29.53 v28.26,28.42 | v18.26,13.97 v27.46,13.97
  Bottom 0.406: v28.26,28.42 28.26,16.35 27.46,15.4 v27.46,13.97 | v18.26,13.97 18.26,8.1 JP1.6
PA6  (via drill 0.5)
  Top 0.406: IC4.4 34.18,27.73 33.34,28.57 30.16,28.57 v29.37,27.78 | v20.64,16.99 v29.21,16.99
  Bottom 0.406: v29.37,27.78 29.37,17.14 v29.21,16.99 | v20.64,16.99 20.64,7.62 20.32,7.3 20.32,5.08 JP1.7
PA7  (via drill 0.5)
  Top 0.406: IC4.5 33.87,26.93 33.34,27.46 30.8,27.46 v30.48,27.15 | v19.68,15.56 v29.37,15.56
  Bottom 0.406: v30.48,27.15 30.48,16.67 v29.37,15.56 | JP1.8 19.05,7.78 19.68,8.41 v19.68,15.56
PB0  (via drill 0.5)
  Top 0.406: IC4.6 33.56,26.13 33.18,26.51 31.75,26.51 v31.59,26.35
  Bottom 0.406: v31.59,26.35 31.59,14.92 24.92,8.26 24.92,5.56 JP3.1
PB1  (via drill 0.5)
  Top 0.406: IC4.7 32.79,25.33 v32.7,25.4
  Bottom 0.406: v32.7,25.4 32.7,14.45 26.67,8.41 JP3.2
PB2  (via drill 0.5)
  Top 0.406: v30.48,8.73 30.48,5.24 JP3.3 | IC4.8 37.38,24.53 v38.73,23.18
  Bottom 0.406: v30.48,8.73 37.62,15.72 37.62,21.11 38.73,22.23 v38.73,23.18
PB3  (via drill 0.5)
  Top 0.406: IC4.9 36.59,23.73 v37.15,23.18
  Bottom 0.406: v37.15,23.18 37.15,22.07 35.56,20.48 35.56,15.56 29.21,9.21 JP3.4
PC0
  Top 0.406: IC4.16 35.43,7.75 JP2.1
PC1
  Top 0.406: IC4.17 37.18,8.54 JP2.2
PC2
  Top 0.406: IC4.18 37.98,9.8 40.64,7.14 40.64,5.08 JP2.3
PC3
  Top 0.406: IC4.19 38.78,10.59 41.91,7.46 JP2.4
PC4
  Top 0.406: IC4.20 39.58,11.06 43.18,7.46 43.18,5.08 JP2.5
PC5
  Top 0.406: IC4.21 40.38,11.53 44.45,7.46 JP2.6
PC6
  Top 0.406: IC4.22 41.18,12 45.72,7.46 45.72,5.08 JP2.7
PC7
  Top 0.406: IC4.23 41.98,12.47 46.99,7.46 JP2.8
PD0  (via drill 0.5)
  Top 0.406: v60.33,18.57 69.69,18.57 76.52,25.4 76.52,28.03 FM1.3 | IC4.26 44.38,18.5 44.93,19.05 v44.93,19.53 | v44.93,19.53
  Bottom 0.406: v60.33,18.57 60.33,13.65 53.02,13.65 47.78,18.89 45.72,18.89 45.24,19.53 v44.93,19.53
PD1  (via drill 0.5)
  Top 0.406: FM1.4 74.55,25.66 68.74,19.84 v59.05,19.84 | IC4.27 45.24,16.44 45.24,17.78 46.51,19.05 v46.51,20
  Bottom 0.406: v59.05,19.84 59.05,15.08 53.02,15.08 48.1,20 v46.51,20
PD2  (via drill 0.5)
  Top 0.406: IC4.28 45.98,15.02 v45.88,14.92
  Bottom 0.406: v45.88,14.92 38.26,14.92 30.48,7.14 30.48,5.08 JP3.5
PD3  (via drill 0.5)
  Top 0.406: IC4.29 46.78,11.54 v46.67,11.43
  Bottom 0.406: v46.67,11.43 36.83,11.43 JP3.6
PE0
  Top 0.406: IC4.36 53.39,20.53 53.98,21.11 68.74,21.11 70.48,22.86 70.48,28 FM1.6
PE1
  Top 0.406: IC4.37 53.08,21.33 53.66,21.91 66.2,21.91 68.58,24.29 68.58,28.04 FM1.7
PE4  (via drill 0.5)
  Top 0.406: v57.47,16.19 73.82,16.19 76.52,13.49 76.52,12.1 FM1.14 | IC4.40 53.9,23.73 54.45,23.18 v57.47,23.18
  Bottom 0.406: v57.47,16.19 v57.47,23.18
PE5  (via drill 0.5)
  Top 0.406: IC4.41 54.84,24.53 v55.24,24.29 | v66.52,25.56 66.52,28.03 FM1.8
  Bottom 0.406: v55.24,24.29 65.25,24.29 v66.52,25.56
PF0
  Top 0.406: IC4.46 52.34,28.53 53.66,29.84 64.14,29.84 65.34,31.05 IC1.4
PF1  (via drill 0.5)
  Top 0.406: IC4.47 52.03,29.33 53.5,30.8 63.5,30.8 v63.98,31.27 | v65.25,49.21 65.25,52.51 IC1.44
  Bottom 0.406: v63.98,31.27 63.98,47.94 v65.25,49.21
PF4  (via drill 0.5)
  Top 0.406: IC4.50 48.38,32.98 48.74,33.34 58.42,33.34 v58.74,33.66 | v58.9,47.62 67.63,47.62 70.42,50.41 IC1.40
  Bottom 0.406: v58.74,33.66 58.74,47.47 v58.9,47.62
PF6
  Top 0.406: IC4.54 45.18,35.97 46.04,36.83 47.62,36.83 47.62,38.42 R2.2 | R2.2
PF7
  Top 0.406: IC4.55 44.38,36.44 45.56,37.62 R1.2
RESET  (via drill 0.5)
  Top 0.406: IC4.57 42.78,29.37 v42.7,28.73 | v16.67,24.29 v33.66,24.29
  Bottom 0.406: JTAG/PDI.6 12.06,17.78 16.67,17.78 v16.67,24.29 | v42.7,28.73 42.7,24.29 v33.66,24.29
RXE0  (via drill 0.5)
  Top 0.406: 50.87,22.07 IC4.38 41.53,22.13 v38.26,25.4 | IC5.1 20.89,25.62 v20.8,25.72
  Bottom 0.406: v20.8,25.72 20.64,25.88 20.64,35.08 21.91,36.35 26.67,36.35 37.78,25.4 v38.26,25.4
RXF  (via drill 0.5)
  Top 0.406: IC4.48 51.56,30.13 53.18,31.75 61.75,31.75 v62.23,32.23 | IC1.46 62.71,52.51 v62.71,49.05
  Bottom 0.406: v62.23,32.23 62.23,48.58 v62.71,49.05
SCKD
  Top 0.406: IC4.33 50.93,17.65 53.5,15.08 71.28,15.08 72.55,13.81 FM1.12
SSD
  Top 0.406: IC4.30 47.58,12.74 52.23,8.1 73.66,8.1 74.61,9.37 74.61,12 FM1.13
TCK
  Top 0.406: IC4.12 35.43,21.27 16.67,21.27 16.67,14.76 JTAG/PDI.1
TDI
  Top 0.406: JTAG/PDI.9 13.34,22.13 IC4.11
TDO  (via drill 0.5)
  Top 0.406: v18.1,15.4 18.1,20.48 35.43,20.48 IC4.13 37.62,20.53 37.62,20.8 38.1,21.27 v39.53,21.27 | v44.13,28.89 43.58,29.53 IC4.56
  Bottom 0.406: v39.53,21.27 44.13,21.27 v44.13,28.89 | v18.1,15.4 14.76,15.4 JTAG/PDI.3
TMS  (via drill 0.5)
  Top 0.406: v18.1,23.18 18.1,22.93 IC4.10
  Bottom 0.406: JTAG/PDI.5 13.34,16.67 18.1,16.67 v18.1,23.18
TOSC1
  Top 0.406: IC4.43 56.85,26.13 MS3V-T1R.P$2 58.81,28.1 C8.1 59.69,27.94
TOSC2
  Top 0.406: C9.1 58.9,23.34 MS3V-T1R.P$3 56.91,25.33 IC4.42
TXE0  (via drill 0.5)
  Top 0.406: IC5.5 20.44,28.22 v19.53,27.3 | v39.69,25.56 42.32,22.93 IC4.39
  Bottom 0.406: v19.53,27.3 19.53,36.04 20.8,37.31 27.94,37.31 v39.69,25.56
TXF  (via drill 0.5)
  Top 0.406: IC4.49 51.56,31.88 52.23,32.54 60.01,32.54 v60.33,32.86 | v63.98,50.32 63.98,52.51 IC1.45
  Bottom 0.406: v60.33,32.86 60.33,50.32 v63.98,50.32

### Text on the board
Top: V1.0
_tplace: TCP | RX/TX | +5V | Acces Point | JTAG/PDI | IC | PA1 | PA3 | PA5 | PA7 | GND | PB1 | PB3 | PD3 | GND | PC1 | PC3 | PC5 | PC7 | GND | V1.0 | WIFI Control 433 | PA0 | PA2 | PA4 | PA6 | 3V3 | PB0 | PB2 | PD2 | 3V3 | PC0 | PC2 | PC4 | PC6 | 3V3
